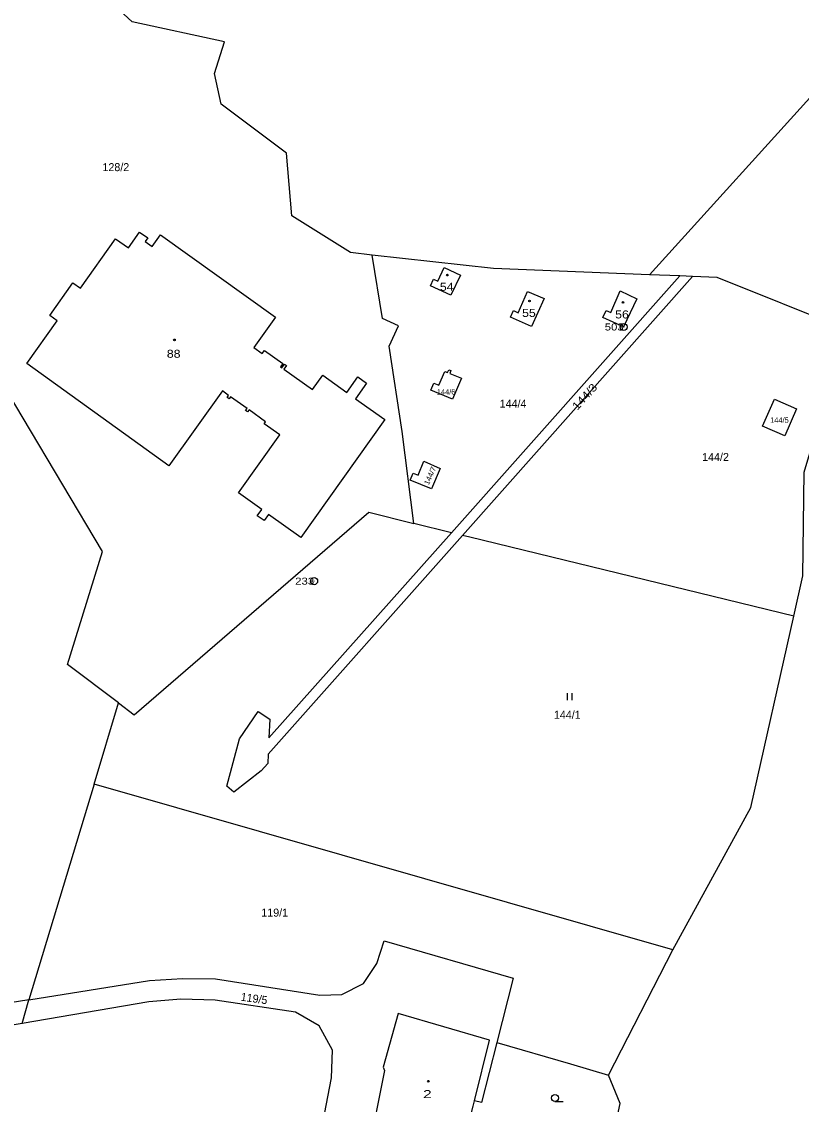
# Model space of a CAD drawing. Extents: x -632162 to -629607, y -1101195 to -1098670.
# Drawn here: x -631825.5 to -631660, y -1099165 to -1098935.2 of the extents above; entities that cross this region are included whole.
import ezdxf
from ezdxf.enums import TextEntityAlignment as Align

# ---------------------------------------------------------------- set-up
doc = ezdxf.new("R2010")
doc.units = 0
doc.header["$LTSCALE"] = 0.68
for name, color, linetype, lineweight in [('1', 7, 'Continuous', 25), ('3', 7, 'Continuous', 25), ('5', 7, 'Continuous', 25), ('8', 7, 'Continuous', 25)]:
    doc.layers.add(name, color=color, linetype=linetype, lineweight=lineweight)
doc.layers.add('2', color=7, linetype='Continuous')

msp = doc.modelspace()

# ---------------------------------------------------------------- linework, layer by layer
at = {"layer": '1'}
for p, q in [((-631537.86, -1098818.43), (-631692.28, -1098988.88)), ((-631683.14, -1098989.26), (-631731.96, -1099044.23)), ((-631685.82, -1098989.15), (-631692.28, -1098988.88)), ((-631810.18, -1099097.04), (-631804.98, -1099079.81)), ((-631721.2, -1099138.26), (-631724.69, -1099151.89)), ((-631825.46, -1099147.85), (-631823.99, -1099142.85))]:
    msp.add_line(p, q, dxfattribs=at)
for points in [[(-631751.13, -1098984.71), (-631755.76, -1098984.2), (-631768.22, -1098976.36), (-631769.31, -1098963.09), (-631783.22, -1098952.7), (-631784.58, -1098946.17), (-631782.47, -1098939.42), (-631802.1, -1098935.2), (-631813.94, -1098924.18), (-631805.21, -1098911.68)], [(-631747.56, -1099004.03), (-631745.56, -1098999.72), (-631748.97, -1098998.15), (-631751.13, -1098984.71)], [(-631692.28, -1098988.88), (-631725.38, -1098987.55), (-631751.13, -1098984.71)], [(-631683.14, -1098989.26), (-631685.82, -1098989.15), (-631734.29, -1099043.66)], [(-631650.36, -1099000.53), (-631677.9, -1098989.47), (-631683.14, -1098989.26)], [(-631661.63, -1099061.36), (-631659.71, -1099052.82), (-631659.46, -1099030.83), (-631650.36, -1099000.53)], [(-631742.29, -1099041.68), (-631744.75, -1099022.16), (-631747.56, -1099004.03)], [(-631804.98, -1099079.81), (-631815.84, -1099071.64), (-631808.37, -1099047.63), (-631833.68, -1099005.17)], [(-631735.11, -1099009.66), (-631734.86, -1099009.07), (-631734.42, -1099009.25), (-631734.66, -1099009.84), (-631732.2, -1099010.85), (-631734.09, -1099015.34), (-631738.69, -1099013.43), (-631738.06, -1099011.91), (-631736.95, -1099012.34)], [(-631736.95, -1099012.34), (-631735.72, -1099009.41), (-631735.11, -1099009.66)], [(-631804.98, -1099079.81), (-631801.66, -1099082.31), (-631751.81, -1099039.33), (-631742.29, -1099041.68)], [(-631773.04, -1099087.24), (-631734.29, -1099043.66), (-631742.29, -1099041.68)], [(-631661.63, -1099061.36), (-631730.4, -1099044.61), (-631731.96, -1099044.23), (-631773.22, -1099090.68)], [(-631687.33, -1099132.23), (-631670.76, -1099101.98), (-631661.63, -1099061.36)], [(-631773.22, -1099090.68), (-631773.32, -1099092.69), (-631774.67, -1099094.2), (-631780.47, -1099098.77), (-631782.02, -1099097.46), (-631779.3, -1099087.43), (-631775.32, -1099081.6), (-631772.83, -1099083.23), (-631773.04, -1099087.24)], [(-631687.33, -1099132.23), (-631810.18, -1099097.04), (-631823.99, -1099142.85), (-631798.44, -1099138.73)], [(-631798.44, -1099138.73), (-631791.4, -1099138.29), (-631784.41, -1099138.41), (-631762.24, -1099141.83), (-631757.6, -1099141.71), (-631752.99, -1099139.35), (-631750.16, -1099135.13), (-631748.57, -1099130.33), (-631721.2, -1099138.26)], [(-631724.69, -1099151.89), (-631709.03, -1099156.47), (-631700.96, -1099158.83), (-631687.33, -1099132.23)], [(-631798.56, -1099143.3), (-631825.46, -1099147.85), (-631831.96, -1099148.95), (-631851.51, -1099153.18)], [(-631823.99, -1099142.85), (-631848.27, -1099146.77), (-631849.06, -1099146.32)], [(-631751.98, -1099175.29), (-631762.35, -1099172.67), (-631759.79, -1099159.42), (-631759.55, -1099153.52), (-631762.37, -1099148.37), (-631767.41, -1099145.48), (-631784.49, -1099142.91), (-631791.78, -1099142.74), (-631798.56, -1099143.3)], [(-631729.42, -1099164.29), (-631726.24, -1099151.44), (-631745.62, -1099145.76), (-631748.79, -1099157.18), (-631748.51, -1099157.88), (-631751.98, -1099175.29)], [(-631724.69, -1099151.89), (-631727.95, -1099164.65), (-631729.42, -1099164.29)], [(-631702.64, -1099184.24), (-631698.52, -1099164.87), (-631700.96, -1099158.83)], [(-631730.88, -1099170.16), (-631729.7, -1099165.43), (-631729.42, -1099164.29)]]:
    msp.add_lwpolyline(points, dxfattribs=at)
for points in [[(-631819.58, -1098997.55), (-631814.66, -1098990.64), (-631813.07, -1098991.77), (-631805.59, -1098981.27), (-631802.87, -1098983.18), (-631800.53, -1098979.84), (-631798.76, -1098981.08), (-631799.3, -1098981.85), (-631797.84, -1098982.87), (-631796.1, -1098980.41), (-631771.66, -1098997.9), (-631776.29, -1099004.36), (-631774.49, -1099005.64), (-631773.99, -1099004.95), (-631770.11, -1099007.74), (-631770.61, -1099008.43), (-631770.32, -1099008.63), (-631769.78, -1099007.87), (-631769.34, -1099008.19), (-631769.88, -1099008.95), (-631763.83, -1099013.29), (-631761.64, -1099010.24), (-631756.54, -1099013.88), (-631754.2, -1099010.58), (-631752.31, -1099011.93), (-631754.65, -1099015.22), (-631748.43, -1099019.65), (-631766.3, -1099044.67), (-631773.13, -1099039.77), (-631774.07, -1099041.08), (-631775.53, -1099040.05), (-631774.59, -1099038.74), (-631779.53, -1099035.21), (-631770.74, -1099022.91), (-631774.08, -1099020.52), (-631773.78, -1099020.09), (-631777.28, -1099017.59), (-631777.59, -1099018.02), (-631778, -1099017.73), (-631777.69, -1099017.3), (-631781.19, -1099014.79), (-631781.5, -1099015.22), (-631781.91, -1099014.93), (-631781.6, -1099014.5), (-631782.91, -1099013.57), (-631794.28, -1099029.5), (-631824.44, -1099007.75), (-631817.99, -1098998.68)], [(-631738.13, -1098989.84), (-631737.21, -1098990.25), (-631735.87, -1098987.37), (-631732.41, -1098988.97), (-631734.42, -1098993.21), (-631738.77, -1098991.25)], [(-631717.34, -1098999.91), (-631721.76, -1098997.91), (-631721.12, -1098996.49), (-631720.12, -1098997), (-631718.17, -1098992.43), (-631714.64, -1098993.93)], [(-631700.45, -1098996.93), (-631698.47, -1098992.34), (-631694.95, -1098993.98), (-631697.75, -1098999.98), (-631702.15, -1098998), (-631701.49, -1098996.48)], [(-631663.57, -1099023.12), (-631668.26, -1099021.04), (-631665.73, -1099015.31), (-631661.08, -1099017.34)], [(-631742.42, -1099031.01), (-631741.4, -1099031.45), (-631740.15, -1099028.5), (-631736.69, -1099030), (-631738.57, -1099034.35), (-631743.07, -1099032.5)]]:
    msp.add_lwpolyline(points, close=True, dxfattribs=at)
at = {"layer": '3'}
for p, q in [((-631709.691, -1099079.22), (-631709.691, -1099077.72)), ((-631708.69, -1099079.22), (-631708.69, -1099077.72)), ((-631712.333, -1099164.44), (-631710.583, -1099164.44))]:
    msp.add_line(p, q, dxfattribs=at)
msp.add_circle((-631712.3329, -1099163.6898), 0.75, dxfattribs=at)
at = {"layer": '5'}
for centre in [(-631735.1668, -1098988.9792), (-631717.7368, -1098994.4692), (-631697.8868, -1098994.7692), (-631793.1068, -1099002.7292), (-631739.2168, -1099160.1292)]:
    msp.add_circle(centre, 0.175, dxfattribs=at)
at = {"layer": '8'}
for centre, radius in [((-631697.75, -1098999.9798), 0.75), ((-631697.75, -1098999.9798), 0.03), ((-631763.46, -1099053.9498), 0.75), ((-631763.46, -1099053.9498), 0.75), ((-631763.46, -1099053.9498), 0.75), ((-631763.46, -1099053.9498), 0.03), ((-631763.46, -1099053.9498), 0.03), ((-631763.46, -1099053.9498), 0.03)]:
    msp.add_circle(centre, radius, dxfattribs=at)

# ---------------------------------------------------------------- texts
at = {"layer": '2'}
for s, height, p in [('128/2', 1.7, (-631805.55, -1098966.9)), ('144/6', 1.14, (-631735.439, -1099014.33)), ('144/4', 1.7, (-631721.23, -1099017.12)), ('144/5', 1.14, (-631664.679, -1099020.32)), ('144/2', 1.7, (-631678.25, -1099028.44)), ('144/1', 1.7, (-631709.72, -1099083.18)), ('119/1', 1.7, (-631771.83, -1099125.18))]:
    msp.add_text(s, height=height, dxfattribs=at).set_placement(p, align=Align.CENTER)
for s, width, p in [('54', 1.15, (-631735.31, -1098992.3)), ('55', 1.15, (-631717.86, -1098997.85)), ('56', 1.15, (-631698.1, -1098998.17)), ('88', 1.15, (-631793.27, -1099006.52)), ('2', 1.45, (-631739.42, -1099163.72))]:
    msp.add_text(s, height=1.7, dxfattribs=dict(at, width=width)).set_placement(p, align=Align.CENTER)
for s, height, rotation, width, p in [('144/3', 1.7, 48, 1.15, (-631705.3968, -1099015.3588)), ('144/7', 1.14, 66, 1.05, (-631738.3197, -1099031.8063))]:
    msp.add_text(s, height=height, rotation=rotation, dxfattribs=dict(at, width=width)).set_placement(p, align=Align.CENTER)
msp.add_text('119/5', height=1.7, rotation=352, dxfattribs=at).set_placement((-631776.3088, -1099143.4021), align=Align.CENTER)
at = {"layer": '8', "width": 1.2}
for s, p in [('503', (-631697.75, -1099000.73)), ('233', (-631763.46, -1099054.7)), ('233', (-631763.46, -1099054.7)), ('233', (-631763.46, -1099054.7))]:
    msp.add_text(s, height=1.5, dxfattribs=at).set_placement(p, align=Align.RIGHT)

doc.saveas('drawing.dxf')
